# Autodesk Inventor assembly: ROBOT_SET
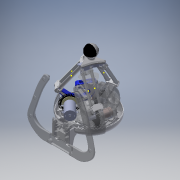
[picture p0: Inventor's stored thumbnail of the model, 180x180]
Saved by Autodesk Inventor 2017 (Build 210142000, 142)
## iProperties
Created: 2013-10
Part Number: ROBOT_SET
Material: Générique
Document SubType Name: Assembly
Designer: Bruno
Sending System: SolidWorks 2013
Last Author: christophe
Last Saved: 2014-02-15
Author: Bruno
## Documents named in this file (7)
- D:\Cours\1-Cours-2018-19\1Ssi\7- EDC-mvt\Haptique-2017\Reel-Inventor\ROBOT_SET.iam
- D:\Cours\1-Cours-2018-19\1Ssi\7- EDC-mvt\Haptique-2017\Reel-Inventor\bati.iam
- D:\Cours\Systèmes\SI\Robot Haptique\Documentations_pedagogique\Modèle solidworks\Reel-Inventor\BIELLE PARALLELOGRAMME.iam
- D:\Cours\Systèmes\SI\Robot Haptique\Documentations_pedagogique\Modèle solidworks\Reel-Inventor\joint.iam
- D:\Cours\Systèmes\SI\Robot Haptique\Documentations_pedagogique\Modèle solidworks\Reel-Inventor\bras.iam
- D:\Cours\Systèmes\SI\Robot Haptique\Documentations_pedagogique\Modèle solidworks\Reel-Inventor\ROTOR.iam
- D:\Cours\1-Cours-2018-19\1Ssi\7- EDC-mvt\Haptique-2017\Reel-Inventor\manette-finie.iam
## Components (20 placed, 6 different names)
1. bati:1 [sub-assembly] — Placage:1, Placage:3, Placage:5, Placage:6, Placage:7, Placage:8, Placage:11, Placage:12, Placage:13, Placage:16, Placage:17
2. BIELLE PARALLELOGRAMME:3 [sub-assembly] — Logement:6, Logement:7
3. joint:3 [sub-assembly] — Logement:5, Logement:6, Logement:19
4. bras:2 [sub-assembly] — Placage:8, Logement:22, Tangente:5, Affleurement:3
5. BIELLE PARALLELOGRAMME:4 [sub-assembly] — Logement:5, Logement:8
6. joint:4 [sub-assembly] — Logement:7, Logement:8, Logement:22
7. bras:5 [sub-assembly] — Tangente:2, Logement:16, Placage:6, Placage:7
8. bras:6 [sub-assembly] — Logement:17, Placage:5, Placage:13, Tangente:6, Placage:14, Placage:15
9. BIELLE PARALLELOGRAMME:9 [sub-assembly] — Logement:10, Logement:12
10. BIELLE PARALLELOGRAMME:10 [sub-assembly] — Logement:3, Logement:4
11. BIELLE PARALLELOGRAMME:11 [sub-assembly] — Logement:1, Logement:2
12. BIELLE PARALLELOGRAMME:12 [sub-assembly] — Logement:9, Logement:11
13. joint:9 [sub-assembly] — Logement:11, Logement:12, Logement:21
14. joint:10 [sub-assembly] — Logement:2, Logement:3, Logement:17, Placage:14, Placage:15
15. joint:11 [sub-assembly] — Logement:1, Logement:4, Logement:20
16. joint:12 [sub-assembly] — Logement:9, Logement:10, Logement:16
17. ROTOR:1 [sub-assembly] — Tangente:6, Placage:16, Placage:17
18. ROTOR:2 [sub-assembly] — Tangente:2, Placage:1, Placage:12
19. ROTOR:3 [sub-assembly] — Placage:3, Tangente:5, Placage:11, Affleurement:3
20. manette-finie:1 [sub-assembly] — Logement:19, Logement:20, Logement:21
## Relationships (35: Insert 18, Mate 13, Tangent 3, Flush 1)
- Logement:1 [Insert]: BIELLE PARALLELOGRAMME:11 ↔ joint:11
- Logement:2 [Insert]: BIELLE PARALLELOGRAMME:11 ↔ joint:10
- Logement:3 [Insert]: BIELLE PARALLELOGRAMME:10 ↔ joint:10
- Logement:4 [Insert]: BIELLE PARALLELOGRAMME:10 ↔ joint:11
- Logement:5 [Insert]: joint:3 ↔ BIELLE PARALLELOGRAMME:4
- Logement:6 [Insert]: BIELLE PARALLELOGRAMME:3 ↔ joint:3
- Logement:7 [Insert]: BIELLE PARALLELOGRAMME:3 ↔ joint:4
- Logement:8 [Insert]: BIELLE PARALLELOGRAMME:4 ↔ joint:4
- Logement:9 [Insert]: BIELLE PARALLELOGRAMME:12 ↔ joint:12
- Logement:10 [Insert]: BIELLE PARALLELOGRAMME:9 ↔ joint:12
- Logement:11 [Insert]: BIELLE PARALLELOGRAMME:12 ↔ joint:9
- Logement:12 [Insert]: BIELLE PARALLELOGRAMME:9 ↔ joint:9
- Tangente:2: bras:5 ↔ ROTOR:2
- Placage:1 [Mate]: bati:1 ↔ ROTOR:2
- Placage:3 [Mate]: bati:1 ↔ ROTOR:3
- Logement:16 [Insert]: bras:5 ↔ joint:12
- Logement:17 [Insert]: bras:6 ↔ joint:10
- Placage:5 [Mate]: bati:1 ↔ bras:6
- Placage:6 [Mate]: bati:1 ↔ bras:5
- Placage:7 [Mate]: bati:1 ↔ bras:5
- Placage:8 [Mate]: bati:1 ↔ bras:2
- Logement:19 [Insert]: joint:3 ↔ manette-finie:1
- Logement:20 [Insert]: joint:11 ↔ manette-finie:1
- Logement:21 [Insert]: joint:9 ↔ manette-finie:1
- Logement:22 [Insert]: bras:2 ↔ joint:4
- Tangente:5: bras:2 ↔ ROTOR:3
- Placage:11 [Mate]: bati:1 ↔ ROTOR:3
- Affleurement:3 [Flush]: bras:2 ↔ ROTOR:3
- Placage:12 [Mate]: bati:1 ↔ ROTOR:2
- Placage:13 [Mate]: bati:1 ↔ bras:6
- Tangente:6: bras:6 ↔ ROTOR:1
- Placage:14 [Mate]: bras:6 ↔ joint:10
- Placage:15 [Mate]: bras:6 ↔ joint:10
- Placage:16 [Mate]: bati:1 ↔ ROTOR:1
- Placage:17 [Mate]: bati:1 ↔ ROTOR:1
